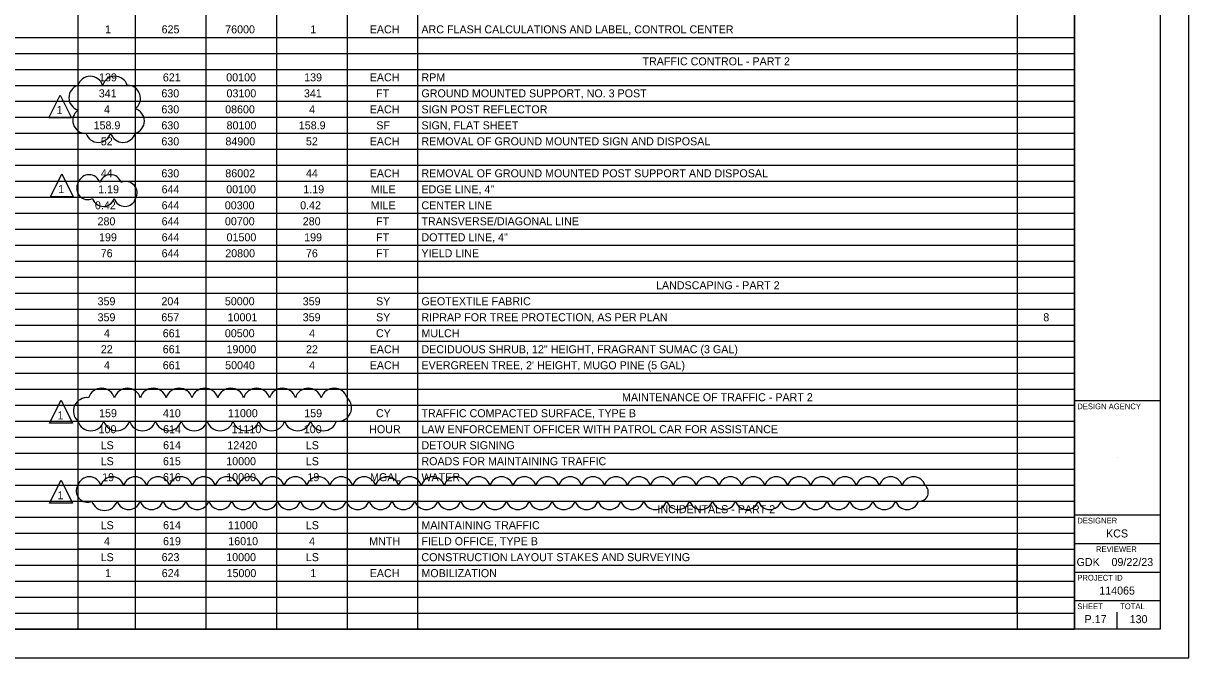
# Model space of a CAD drawing. Extents: x 0 to 76.3, y 0 to 22.
# Drawn here: x 13.61 to 34, y 0 to 11.11 of the extents above; entities that cross this region are included whole.
import ezdxf

# ---------------------------------------------------------------- set-up
doc = ezdxf.new("R2010")
doc.units = 0
for name, color, linetype in [('Default', 7, 'Continuous'), ('MU_Markup_Cloud', 7, 'Continuous'), ('SH_Border', 7, 'Continuous'), ('SH_Cut_Line', 7, 'Continuous'), ('SH_Data', 7, 'Continuous')]:
    doc.layers.add(name, color=color, linetype=linetype)

msp = doc.modelspace()

# ---------------------------------------------------------------- linework, layer by layer
at = {"layer": 'Default'}
for p, q in [((15.566, 21.5), (15.566, 0.5)), ((16.801, 21.5), (16.801, 0.5)), ((18.036, 21.5), (18.036, 0.5)), ((19.272, 21.5), (19.272, 0.5)), ((20.507, 21.5), (20.507, 0.5)), ((30.999, 21.5), (30.999, 0.5)), ((32.004, 21.5), (32.004, 0.5)), ((14.561, 20.94), (14.561, 0.5)), ((1.5, 10.86), (32.004, 10.86)), ((1.5, 10.58), (32.004, 10.58)), ((1.5, 10.3), (32.004, 10.3)), ((1.5, 10.02), (32.004, 10.02)), ((1.5, 9.74), (32.004, 9.74)), ((1.5, 9.46), (32.004, 9.46)), ((1.5, 9.18), (32.004, 9.18)), ((1.5, 8.9), (32.004, 8.9)), ((1.5, 8.62), (32.004, 8.62)), ((1.5, 8.34), (32.004, 8.34)), ((1.5, 8.06), (32.004, 8.06)), ((1.5, 7.78), (32.004, 7.78)), ((1.5, 7.5), (32.004, 7.5)), ((1.5, 7.22), (32.004, 7.22)), ((1.5, 6.94), (32.004, 6.94)), ((1.5, 6.66), (32.004, 6.66)), ((1.5, 6.38), (32.004, 6.38)), ((1.5, 6.1), (32.004, 6.1)), ((1.5, 5.82), (32.004, 5.82)), ((1.5, 5.54), (32.004, 5.54)), ((1.5, 5.26), (32.004, 5.26)), ((1.5, 4.98), (32.004, 4.98)), ((1.5, 4.7), (32.004, 4.7)), ((1.5, 4.42), (32.004, 4.42)), ((1.5, 4.14), (32.004, 4.14)), ((1.5, 3.86), (32.004, 3.86)), ((1.5, 3.58), (32.004, 3.58)), ((1.5, 3.3), (32.004, 3.3)), ((1.5, 3.02), (32.004, 3.02)), ((1.5, 2.74), (32.004, 2.74)), ((1.5, 2.46), (32.004, 2.46)), ((1.5, 2.18), (32.004, 2.18)), ((1.5, 1.9), (32.004, 1.9)), ((1.5, 1.62), (32.004, 1.62)), ((1.5, 1.34), (32.004, 1.34)), ((1.5, 1.06), (32.004, 1.06)), ((1.5, 0.78), (32.004, 0.78)), ((1.5, 0.5), (32.004, 0.5))]:
    msp.add_line(p, q, dxfattribs=at)
msp.add_lwpolyline([(30.999, 0.78), (30.999, 1.9), (14.561, 1.9), (14.561, 0.78)], close=True, dxfattribs=at)
at = {"layer": 'MU_Markup_Cloud'}
for points in [[(14.051, 9.45), (14.251, 9.85), (14.451, 9.45)], [(14.079, 8.068), (14.279, 8.468), (14.479, 8.068)], [(14.066, 4.106), (14.266, 4.506), (14.466, 4.106)], [(14.066, 2.706), (14.266, 3.106), (14.466, 2.706)]]:
    msp.add_lwpolyline(points, close=True, dxfattribs=at)
for centre, radius, start, end in [((14.629, 9.804), 0.226, 107.5, 252.5), ((14.777, 9.952), 0.226, 17.5, 162.5), ((15.209, 9.952), 0.226, 17.5, 162.5), ((15.431, 9.794), 0.226, 306.5256, 91.5256), ((14.696, 9.406), 0.226, 126.5256, 271.5256), ((15.498, 9.396), 0.226, 287.5, 72.5), ((14.918, 9.248), 0.226, 197.5, 342.5), ((15.35, 9.248), 0.226, 197.5, 342.5), ((14.756, 8.258), 0.197, 17.5, 162.5), ((15.132, 8.258), 0.197, 17.5, 162.5), ((14.737, 8.217), 0.197, 149.4347, 294.4347), ((15.402, 8.138), 0.197, 329.4347, 114.4347), ((15.007, 8.097), 0.197, 197.5, 342.5), ((15.384, 8.097), 0.197, 197.5, 342.5), ((14.975, 4.48), 0.237, 17.5, 162.5), ((15.427, 4.48), 0.237, 17.5, 162.5), ((15.88, 4.48), 0.237, 17.5, 162.5), ((16.332, 4.48), 0.237, 17.5, 162.5), ((16.784, 4.48), 0.237, 17.5, 162.5), ((17.236, 4.48), 0.237, 17.5, 162.5), ((17.689, 4.48), 0.237, 17.5, 162.5), ((18.141, 4.48), 0.237, 17.5, 162.5), ((18.593, 4.48), 0.237, 17.5, 162.5), ((19.046, 4.48), 0.237, 17.5, 162.5), ((14.72, 4.316), 0.237, 82.9631, 227.9631), ((19.113, 4.375), 0.237, 262.9631, 47.9631), ((14.787, 4.211), 0.237, 197.5, 342.5), ((15.24, 4.211), 0.237, 197.5, 342.5), ((15.692, 4.211), 0.237, 197.5, 342.5), ((16.144, 4.211), 0.237, 197.5, 342.5), ((16.596, 4.211), 0.237, 197.5, 342.5), ((17.049, 4.211), 0.237, 197.5, 342.5), ((17.501, 4.211), 0.237, 197.5, 342.5), ((17.953, 4.211), 0.237, 197.5, 342.5), ((18.406, 4.211), 0.237, 197.5, 342.5), ((18.858, 4.211), 0.237, 197.5, 342.5), ((14.762, 2.957), 0.21, 17.5, 162.5), ((15.162, 2.957), 0.21, 17.5, 162.5), ((15.563, 2.957), 0.21, 17.5, 162.5), ((15.964, 2.957), 0.21, 17.5, 162.5), ((16.364, 2.957), 0.21, 17.5, 162.5), ((16.765, 2.957), 0.21, 17.5, 162.5), ((17.166, 2.957), 0.21, 17.5, 162.5), ((17.566, 2.957), 0.21, 17.5, 162.5), ((17.967, 2.957), 0.21, 17.5, 162.5), ((18.368, 2.957), 0.21, 17.5, 162.5), ((18.768, 2.957), 0.21, 17.5, 162.5), ((19.169, 2.957), 0.21, 17.5, 162.5), ((19.57, 2.957), 0.21, 17.5, 162.5), ((19.971, 2.957), 0.21, 17.5, 162.5), ((20.371, 2.957), 0.21, 17.5, 162.5), ((20.772, 2.957), 0.21, 17.5, 162.5), ((21.173, 2.957), 0.21, 17.5, 162.5), ((21.573, 2.957), 0.21, 17.5, 162.5), ((21.974, 2.957), 0.21, 17.5, 162.5), ((22.375, 2.957), 0.21, 17.5, 162.5), ((22.775, 2.957), 0.21, 17.5, 162.5), ((23.176, 2.957), 0.21, 17.5, 162.5), ((23.577, 2.957), 0.21, 17.5, 162.5), ((23.977, 2.957), 0.21, 17.5, 162.5), ((24.378, 2.957), 0.21, 17.5, 162.5), ((24.779, 2.957), 0.21, 17.5, 162.5), ((25.18, 2.957), 0.21, 17.5, 162.5), ((25.58, 2.957), 0.21, 17.5, 162.5), ((25.981, 2.957), 0.21, 17.5, 162.5), ((26.382, 2.957), 0.21, 17.5, 162.5), ((26.782, 2.957), 0.21, 17.5, 162.5), ((27.183, 2.957), 0.21, 17.5, 162.5), ((27.584, 2.957), 0.21, 17.5, 162.5), ((27.984, 2.957), 0.21, 17.5, 162.5), ((28.385, 2.957), 0.21, 17.5, 162.5), ((28.786, 2.957), 0.21, 17.5, 162.5), ((29.186, 2.957), 0.21, 17.5, 162.5), ((14.727, 2.918), 0.195, 148.5475, 293.5475), ((29.286, 2.898), 0.158, 265.4047, 50.4047), ((15.027, 2.81), 0.233, 197.5, 342.5), ((15.449, 2.803), 0.21, 197.5, 342.5), ((15.85, 2.803), 0.21, 197.5, 342.5), ((16.251, 2.803), 0.21, 197.5, 342.5), ((16.651, 2.803), 0.21, 197.5, 342.5), ((17.052, 2.803), 0.21, 197.5, 342.5), ((17.453, 2.803), 0.21, 197.5, 342.5), ((17.853, 2.803), 0.21, 197.5, 342.5), ((18.254, 2.803), 0.21, 197.5, 342.5), ((18.655, 2.803), 0.21, 197.5, 342.5), ((19.055, 2.803), 0.21, 197.5, 342.5), ((19.456, 2.803), 0.21, 197.5, 342.5), ((19.857, 2.803), 0.21, 197.5, 342.5), ((20.258, 2.803), 0.21, 197.5, 342.5), ((20.658, 2.803), 0.21, 197.5, 342.5), ((21.059, 2.803), 0.21, 197.5, 342.5), ((21.46, 2.803), 0.21, 197.5, 342.5), ((21.86, 2.803), 0.21, 197.5, 342.5), ((22.261, 2.803), 0.21, 197.5, 342.5), ((22.662, 2.803), 0.21, 197.5, 342.5), ((23.062, 2.803), 0.21, 197.5, 342.5), ((23.463, 2.803), 0.21, 197.5, 342.5), ((23.864, 2.803), 0.21, 197.5, 342.5), ((24.264, 2.803), 0.21, 197.5, 342.5), ((24.665, 2.803), 0.21, 197.5, 342.5), ((25.066, 2.803), 0.21, 197.5, 342.5), ((25.467, 2.803), 0.21, 197.5, 342.5), ((25.867, 2.803), 0.21, 197.5, 342.5), ((26.268, 2.803), 0.21, 197.5, 342.5), ((26.669, 2.803), 0.21, 197.5, 342.5), ((27.069, 2.803), 0.21, 197.5, 342.5), ((27.47, 2.803), 0.21, 197.5, 342.5), ((27.871, 2.803), 0.21, 197.5, 342.5), ((28.271, 2.803), 0.21, 197.5, 342.5), ((28.672, 2.803), 0.21, 197.5, 342.5), ((29.073, 2.803), 0.21, 197.5, 342.5)]:
    msp.add_arc(centre, radius, start, end, dxfattribs=at)
at = {"layer": 'SH_Border'}
for p, q in [((32, 0.5), (32, 21.5)), ((32, 4.5), (33.5, 4.5)), ((32, 2.5), (33.5, 2.5)), ((32, 2), (33.5, 2)), ((32, 1.5), (33.5, 1.5)), ((32, 1), (33.5, 1))]:
    msp.add_line(p, q, dxfattribs=at)
msp.add_lwpolyline([(1.5, 21.5), (33.5, 21.5), (33.5, 0.5), (1.5, 0.5)], close=True, dxfattribs=at)
at = {"layer": 'SH_Cut_Line'}
msp.add_lwpolyline([(0, 0), (34, 0), (34, 22), (0, 22)], close=True, dxfattribs=at)
at = {"layer": 'SH_Data'}
for p, q in [((32.75, 3.5), (32.75, 3.5)), ((32.375, 0.675), (32.375, 0.675)), ((32.75, 0.5), (32.75, 0.8))]:
    msp.add_line(p, q, dxfattribs=at)

# ---------------------------------------------------------------- texts
at = {"layer": 'Default'}
for s, p in [('1', (15.037, 10.93)), ('625', (16.026, 10.93)), ('76000', (17.139, 10.93)), ('1', (18.628, 10.93)), ('EACH', (19.668, 10.93)), ('ARC FLASH CALCULATIONS AND LABEL, CONTROL CENTER', (20.573, 10.93)), ('TRAFFIC CONTROL - PART 2', (24.442, 10.37)), ('139', (14.931, 10.09)), ('621', (16.048, 10.09)), ('00100', (17.157, 10.09)), ('139', (18.521, 10.09)), ('EACH', (19.668, 10.09)), ('RPM', (20.573, 10.09)), ('341', (14.927, 9.81)), ('630', (16.022, 9.81)), ('03100', (17.162, 9.81)), ('341', (18.517, 9.81)), ('FT', (19.779, 9.81)), ('GROUND MOUNTED SUPPORT, NO. 3 POST', (20.573, 9.81)), ('4', (15.017, 9.53)), ('630', (16.022, 9.53)), ('08600', (17.138, 9.53)), ('4', (18.608, 9.53)), ('EACH', (19.668, 9.53)), ('SIGN POST REFLECTOR', (20.573, 9.53)), ('158.9', (14.836, 9.25)), ('630', (16.022, 9.25)), ('80100', (17.163, 9.25)), ('158.9', (18.427, 9.25)), ('SF', (19.783, 9.25)), ('SIGN, FLAT SHEET', (20.573, 9.25)), ('52', (14.962, 8.97)), ('630', (16.022, 8.97)), ('84900', (17.143, 8.97)), ('52', (18.552, 8.97)), ('EACH', (19.668, 8.97)), ('REMOVAL OF GROUND MOUNTED SIGN AND DISPOSAL', (20.573, 8.97)), ('44', (14.962, 8.41)), ('630', (16.022, 8.41)), ('86002', (17.141, 8.41)), ('44', (18.552, 8.41)), ('EACH', (19.668, 8.41)), ('REMOVAL OF GROUND MOUNTED POST SUPPORT AND DISPOSAL', (20.573, 8.41)), ('1.19', (14.916, 8.13)), ('644', (16.026, 8.13)), ('00100', (17.157, 8.13)), ('1.19', (18.506, 8.13)), ('MILE', (19.685, 8.13)), ('EDGE LINE, 4"', (20.573, 8.13)), ('0.42', (14.86, 7.85)), ('644', (16.026, 7.85)), ('00300', (17.132, 7.85)), ('0.42', (18.451, 7.85)), ('MILE', (19.685, 7.85)), ('CENTER LINE', (20.573, 7.85)), ('280', (14.905, 7.57)), ('644', (16.026, 7.57)), ('00700', (17.134, 7.57)), ('280', (18.496, 7.57)), ('FT', (19.779, 7.57)), ('TRANSVERSE/DIAGONAL LINE', (20.573, 7.57)), ('199', (14.931, 7.29)), ('644', (16.026, 7.29)), ('01500', (17.163, 7.29)), ('199', (18.521, 7.29)), ('FT', (19.779, 7.29)), ('DOTTED LINE, 4"', (20.573, 7.29)), ('76', (14.961, 7.01)), ('644', (16.026, 7.01)), ('20800', (17.14, 7.01)), ('76', (18.552, 7.01)), ('FT', (19.779, 7.01)), ('YIELD LINE', (20.573, 7.01)), ('LANDSCAPING - PART 2', (24.678, 6.45)), ('359', (14.906, 6.17)), ('204', (16.023, 6.17)), ('50000', (17.133, 6.17)), ('359', (18.496, 6.17)), ('SY', (19.779, 6.17)), ('GEOTEXTILE FABRIC', (20.573, 6.17)), ('359', (14.906, 5.89)), ('657', (16.022, 5.89)), ('10001', (17.181, 5.89)), ('359', (18.496, 5.89)), ('SY', (19.779, 5.89)), ('RIPRAP FOR TREE PROTECTION, AS PER PLAN', (20.573, 5.89)), ('8', (31.456, 5.89)), ('4', (15.017, 5.61)), ('661', (16.046, 5.61)), ('00500', (17.133, 5.61)), ('4', (18.608, 5.61)), ('CY', (19.777, 5.61)), ('MULCH', (20.573, 5.61)), ('22', (14.963, 5.33)), ('661', (16.046, 5.33)), ('19000', (17.162, 5.33)), ('22', (18.553, 5.33)), ('EACH', (19.668, 5.33)), ('DECIDUOUS SHRUB, 12" HEIGHT, FRAGRANT SUMAC (3 GAL)', (20.573, 5.33)), ('4', (15.017, 5.05)), ('661', (16.046, 5.05)), ('50040', (17.138, 5.05)), ('4', (18.608, 5.05)), ('EACH', (19.668, 5.05)), ("EVERGREEN TREE, 2' HEIGHT, MUGO PINE (5 GAL)", (20.573, 5.05)), ('MAINTENANCE OF TRAFFIC - PART 2', (24.083, 4.49)), ('159', (14.932, 4.21)), ('410', (16.049, 4.21)), ('11000', (17.188, 4.21)), ('159', (18.522, 4.21)), ('CY', (19.777, 4.21)), ('TRAFFIC COMPACTED SURFACE, TYPE B', (20.573, 4.21)), ('100', (14.923, 3.93)), ('614', (16.052, 3.93)), ('11110', (17.25, 3.93)), ('100', (18.514, 3.93)), ('HOUR', (19.659, 3.93)), ('LAW ENFORCEMENT OFFICER WITH PATROL CAR FOR ASSISTANCE', (20.573, 3.93)), ('LS', (14.959, 3.65)), ('614', (16.052, 3.65)), ('12420', (17.177, 3.65)), ('LS', (18.55, 3.65)), ('DETOUR SIGNING', (20.573, 3.65)), ('LS', (14.959, 3.37)), ('615', (16.05, 3.37)), ('10000', (17.157, 3.37)), ('LS', (18.55, 3.37)), ('ROADS FOR MAINTAINING TRAFFIC', (20.573, 3.37)), ('19', (14.986, 3.09)), ('616', (16.05, 3.09)), ('10000', (17.157, 3.09)), ('19', (18.577, 3.09)), ('MGAL', (19.674, 3.09)), ('WATER', (20.573, 3.09)), ('INCIDENTALS - PART 2', (24.704, 2.53)), ('LS', (14.959, 2.25)), ('614', (16.052, 2.25)), ('11000', (17.188, 2.25)), ('LS', (18.55, 2.25)), ('MAINTAINING TRAFFIC', (20.573, 2.25)), ('4', (15.017, 1.97)), ('619', (16.051, 1.97)), ('16010', (17.193, 1.97)), ('4', (18.608, 1.97)), ('MNTH', (19.658, 1.97)), ('FIELD OFFICE, TYPE B', (20.573, 1.97)), ('LS', (14.959, 1.69)), ('623', (16.026, 1.69)), ('10000', (17.157, 1.69)), ('LS', (18.55, 1.69)), ('CONSTRUCTION LAYOUT STAKES AND SURVEYING', (20.573, 1.69)), ('1', (15.037, 1.41)), ('624', (16.028, 1.41)), ('15000', (17.163, 1.41)), ('1', (18.628, 1.41)), ('EACH', (19.668, 1.41)), ('MOBILIZATION', (20.573, 1.41))]:
    msp.add_text(s, height=0.14, dxfattribs=at).set_placement(p)
at = {"layer": 'MU_Markup_Cloud'}
for p in [(14.188, 9.517), (14.216, 8.134), (14.204, 4.172), (14.204, 2.772)]:
    msp.add_text('1', height=0.14, dxfattribs=at).set_placement(p)
at = {"layer": 'SH_Data'}
for s, height, p in [('DESIGN AGENCY', 0.1, (32.05, 4.35)), ('DESIGNER', 0.1, (32.05, 2.35)), ('KCS', 0.14, (32.554, 2.105)), ('REVIEWER', 0.1, (32.378, 1.85)), ('GDK', 0.14, (32.038, 1.605)), ('09/22/23', 0.14, (32.649, 1.605)), ('PROJECT ID', 0.1, (32.05, 1.35)), ('114065', 0.14, (32.435, 1.105)), ('SHEET', 0.1, (32.05, 0.85)), ('TOTAL', 0.1, (32.8, 0.85)), ('P.17', 0.14, (32.178, 0.605)), ('130', 0.14, (32.967, 0.605))]:
    msp.add_text(s, height=height, dxfattribs=at).set_placement(p)

doc.saveas('drawing.dxf')
